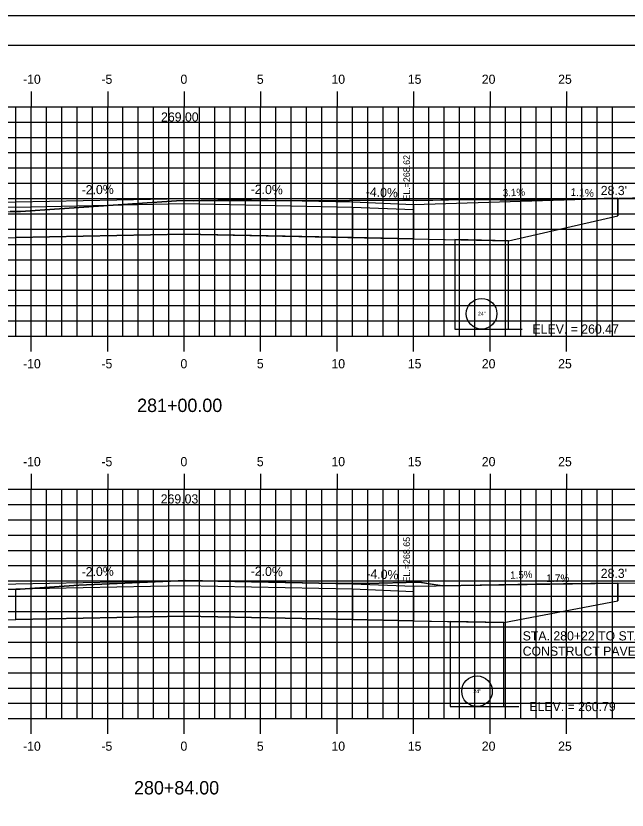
# Model space of a CAD drawing. Extents: x 855344 to 855514, y 366268 to 366378.
# Drawn here: x 855416.1 to 855456.1, y 366326.3 to 366378.2 of the extents above; entities that cross this region are included whole.
import ezdxf

# ---------------------------------------------------------------- set-up
doc = ezdxf.new("R2010")
doc.units = 0
for name, color, linetype in [('ANNOTATION', 7, 'Continuous'), ('BORDER', 7, 'Continuous'), ('D_Roadway_Centerline', 7, 'Continuous'), ('D_Roadway_Centerline_Text', 7, 'Continuous'), ('D_Roadway_Drive_Gravel_RT', 7, 'Continuous'), ('D_Roadway_Drive_SubGrade', 7, 'Continuous'), ('D_Roadway_Edge_Shoulder', 7, 'Continuous'), ('D_Roadway_SubGrade', 7, 'Continuous'), ('D_Text_Monospaced', 7, 'Continuous'), ('D_Text_Standard', 7, 'Continuous'), ('H_V ANNOTATION', 7, 'Continuous'), ('JUNK COM EXC', 7, 'Continuous'), ('junk strct exc', 7, 'Continuous'), ('MAJOR', 7, 'Continuous'), ('MINOR', 7, 'Continuous'), ('PDRAIN', 7, 'Continuous'), ('PLOT BOUNDARY', 7, 'Continuous'), ('S_Roadway_Centerline', 7, 'Continuous')]:
    doc.layers.add(name, color=color, linetype=linetype)

msp = doc.modelspace()

# ---------------------------------------------------------------- linework, layer by layer
at = {"layer": 'BORDER'}
msp.add_line((855512.11, 366376.236), (855352.11, 366376.236), dxfattribs=at)
at = {"layer": 'D_Roadway_Centerline'}
msp.add_lwpolyline([(855416.11, 366366.016), (855427.11, 366366.236), (855438.11, 366366.016)], dxfattribs=at)
at = {"layer": 'D_Roadway_Drive_Gravel_RT'}
for p, q in [((855442.107, 366365.856), (855455.456, 366366.263)), ((855442.107, 366340.888), (855455.456, 366341.093))]:
    msp.add_line(p, q, dxfattribs=at)
at = {"layer": 'D_Roadway_Drive_SubGrade'}
for p, q in [((855455.456, 366366.263), (855455.456, 366365.096)), ((855448.302, 366363.479), (855455.456, 366365.096)), ((855442.107, 366363.603), (855448.302, 366363.479)), ((855455.456, 366341.093), (855455.456, 366339.926)), ((855448.002, 366338.517), (855455.456, 366339.926)), ((855442.107, 366338.635), (855448.002, 366338.517))]:
    msp.add_line(p, q, dxfattribs=at)
at = {"layer": 'D_Roadway_Edge_Shoulder'}
for p, q in [((855442.107, 366365.856), (855442.11, 366365.523)), ((855442.107, 366365.856), (855442.107, 366365.523)), ((855442.107, 366340.888), (855442.11, 366340.556)), ((855442.107, 366340.888), (855442.107, 366340.555))]:
    msp.add_line(p, q, dxfattribs=at)
for points in [[(855411.891, 366365.848), (855416.11, 366366.016), (855427.11, 366366.236), (855438.11, 366366.016), (855442.107, 366365.856)], [(855410.728, 366340.834), (855416.11, 366341.049), (855427.11, 366341.268), (855438.11, 366341.048), (855442.107, 366340.888)]]:
    msp.add_lwpolyline(points, dxfattribs=at)
at = {"layer": 'D_Roadway_SubGrade'}
for points in [[(855416.11, 366365.683), (855411.891, 366365.515), (855411.891, 366363.599), (855416.11, 366363.683)], [(855416.11, 366363.683), (855416.11, 366365.683), (855427.11, 366365.903), (855438.11, 366365.683), (855438.11, 366363.683), (855427.11, 366363.903)], [(855438.11, 366365.683), (855442.11, 366365.523), (855442.11, 366363.603), (855438.11, 366363.683)], [(855416.11, 366338.716), (855416.11, 366340.716), (855427.11, 366340.936), (855438.11, 366340.716), (855438.11, 366338.716), (855427.11, 366338.936)], [(855438.11, 366340.716), (855442.11, 366340.556), (855442.11, 366338.636), (855438.11, 366338.716)]]:
    msp.add_lwpolyline(points, close=True, dxfattribs=at)
at = {"layer": 'D_Text_Standard'}
for points in [[(855448.302, 366357.706), (855448.518, 366357.706), (855449.198, 366357.706)], [(855448.002, 366333.026), (855448.314, 366333.026), (855448.994, 366333.026)]]:
    msp.add_lwpolyline(points, dxfattribs=at)
at = {"layer": 'JUNK COM EXC'}
msp.add_lwpolyline([(855410.891, 366363.579), (855416.11, 366363.683), (855427.11, 366363.903), (855442.11, 366363.603), (855443.107, 366363.583), (855448.302, 366363.479), (855455.456, 366365.096), (855455.456, 366366.263), (855450.069, 366366.134), (855445.427, 366366.167), (855443.109, 366366.119), (855442.313, 366366.102), (855441.388, 366366.135), (855437.92, 366366.106), (855427.725, 366366.096), (855427.071, 366366.108), (855426.605, 366366.089), (855416.406, 366365.387), (855415.725, 366365.379)], dxfattribs=at)
msp.add_lwpolyline([(855409.728, 366340.586), (855409.728, 366338.595), (855416.11, 366338.716), (855427.11, 366338.936), (855438.11, 366338.716), (855443.107, 366338.615), (855448.002, 366338.517), (855455.456, 366339.926), (855455.456, 366341.093), (855450.133, 366341.025), (855443.985, 366340.92), (855443.109, 366341.055), (855442.502, 366341.148), (855438.987, 366341.077), (855437.99, 366341.069), (855437.021, 366341.068), (855427.216, 366341.257), (855420.216, 366340.964), (855416.384, 366340.7), (855413.757, 366340.668), (855411.541, 366340.585)], close=True, dxfattribs=at)
at = {"layer": 'junk strct exc'}
for points in [[(855444.802, 366363.549), (855444.802, 366357.706), (855448.302, 366357.706), (855448.302, 366363.479)], [(855444.502, 366338.587), (855444.502, 366333.026), (855448.002, 366333.026), (855448.002, 366338.517)]]:
    msp.add_lwpolyline(points, close=True, dxfattribs=at)
at = {"layer": 'MAJOR'}
for p, q in [((855417.11, 366373.238), (855417.11, 366372.236)), ((855422.11, 366373.238), (855422.11, 366372.236)), ((855427.11, 366373.238), (855427.11, 366372.236)), ((855432.11, 366373.238), (855432.11, 366372.236)), ((855437.11, 366373.238), (855437.11, 366372.236)), ((855442.11, 366373.238), (855442.11, 366372.236)), ((855447.11, 366373.238), (855447.11, 366372.236)), ((855452.11, 366373.238), (855452.11, 366372.236)), ((855357.11, 366372.236), (855497.11, 366372.236)), ((855357.11, 366372.236), (855497.11, 366372.236)), ((855417.11, 366357.236), (855417.11, 366372.236)), ((855422.11, 366357.236), (855422.11, 366372.236)), ((855427.11, 366357.236), (855427.11, 366372.236)), ((855432.11, 366357.236), (855432.11, 366372.236)), ((855437.11, 366357.236), (855437.11, 366372.236)), ((855442.11, 366357.236), (855442.11, 366372.236)), ((855447.11, 366357.236), (855447.11, 366372.236)), ((855452.11, 366357.236), (855452.11, 366372.236)), ((855357.11, 366367.236), (855497.11, 366367.236)), ((855357.11, 366362.236), (855497.11, 366362.236)), ((855357.11, 366357.236), (855497.11, 366357.236)), ((855357.11, 366357.236), (855497.11, 366357.236)), ((855417.11, 366356.234), (855417.11, 366357.236)), ((855422.11, 366356.234), (855422.11, 366357.236)), ((855427.11, 366356.234), (855427.11, 366357.236)), ((855432.11, 366356.234), (855432.11, 366357.236)), ((855437.11, 366356.234), (855437.11, 366357.236)), ((855442.11, 366356.234), (855442.11, 366357.236)), ((855447.11, 366356.234), (855447.11, 366357.236)), ((855452.11, 366356.234), (855452.11, 366357.236)), ((855417.11, 366348.238), (855417.11, 366347.236)), ((855422.11, 366348.238), (855422.11, 366347.236)), ((855427.11, 366348.238), (855427.11, 366347.236)), ((855432.11, 366348.238), (855432.11, 366347.236)), ((855437.11, 366348.238), (855437.11, 366347.236)), ((855442.11, 366348.238), (855442.11, 366347.236)), ((855447.11, 366348.238), (855447.11, 366347.236)), ((855452.11, 366348.238), (855452.11, 366347.236)), ((855357.11, 366347.236), (855497.11, 366347.236)), ((855357.11, 366347.236), (855497.11, 366347.236)), ((855417.11, 366332.236), (855417.11, 366347.236)), ((855422.11, 366332.236), (855422.11, 366347.236)), ((855427.11, 366332.236), (855427.11, 366347.236)), ((855432.11, 366332.236), (855432.11, 366347.236)), ((855437.11, 366332.236), (855437.11, 366347.236)), ((855442.11, 366332.236), (855442.11, 366347.236)), ((855447.11, 366332.236), (855447.11, 366347.236)), ((855452.11, 366332.236), (855452.11, 366347.236)), ((855357.11, 366342.236), (855497.11, 366342.236)), ((855357.11, 366337.236), (855497.11, 366337.236)), ((855357.11, 366332.236), (855497.11, 366332.236)), ((855357.11, 366332.236), (855497.11, 366332.236)), ((855417.11, 366331.234), (855417.11, 366332.236)), ((855422.11, 366331.234), (855422.11, 366332.236)), ((855427.11, 366331.234), (855427.11, 366332.236)), ((855432.11, 366331.234), (855432.11, 366332.236)), ((855437.11, 366331.234), (855437.11, 366332.236)), ((855442.11, 366331.234), (855442.11, 366332.236)), ((855447.11, 366331.234), (855447.11, 366332.236)), ((855452.11, 366331.234), (855452.11, 366332.236))]:
    msp.add_line(p, q, dxfattribs=at)
at = {"layer": 'MINOR'}
for p, q in [((855416.11, 366357.236), (855416.11, 366372.236)), ((855418.11, 366357.236), (855418.11, 366372.236)), ((855419.11, 366357.236), (855419.11, 366372.236)), ((855420.11, 366357.236), (855420.11, 366372.236)), ((855421.11, 366357.236), (855421.11, 366372.236)), ((855423.11, 366357.236), (855423.11, 366372.236)), ((855424.11, 366357.236), (855424.11, 366372.236)), ((855425.11, 366357.236), (855425.11, 366372.236)), ((855426.11, 366357.236), (855426.11, 366372.236)), ((855428.11, 366357.236), (855428.11, 366372.236)), ((855429.11, 366357.236), (855429.11, 366372.236)), ((855430.11, 366357.236), (855430.11, 366372.236)), ((855431.11, 366357.236), (855431.11, 366372.236)), ((855433.11, 366357.236), (855433.11, 366372.236)), ((855434.11, 366357.236), (855434.11, 366372.236)), ((855435.11, 366357.236), (855435.11, 366372.236)), ((855436.11, 366357.236), (855436.11, 366372.236)), ((855438.11, 366357.236), (855438.11, 366372.236)), ((855439.11, 366357.236), (855439.11, 366372.236)), ((855440.11, 366357.236), (855440.11, 366372.236)), ((855441.11, 366357.236), (855441.11, 366372.236)), ((855443.11, 366357.236), (855443.11, 366372.236)), ((855444.11, 366357.236), (855444.11, 366372.236)), ((855445.11, 366357.236), (855445.11, 366372.236)), ((855446.11, 366357.236), (855446.11, 366372.236)), ((855448.11, 366357.236), (855448.11, 366372.236)), ((855449.11, 366357.236), (855449.11, 366372.236)), ((855450.11, 366357.236), (855450.11, 366372.236)), ((855451.11, 366357.236), (855451.11, 366372.236)), ((855453.11, 366357.236), (855453.11, 366372.236)), ((855454.11, 366357.236), (855454.11, 366372.236)), ((855455.11, 366357.236), (855455.11, 366372.236)), ((855357.11, 366371.236), (855497.11, 366371.236)), ((855357.11, 366370.236), (855497.11, 366370.236)), ((855357.11, 366369.236), (855497.11, 366369.236)), ((855357.11, 366368.236), (855497.11, 366368.236)), ((855357.11, 366366.236), (855497.11, 366366.236)), ((855357.11, 366365.236), (855497.11, 366365.236)), ((855357.11, 366364.236), (855497.11, 366364.236)), ((855357.11, 366363.236), (855497.11, 366363.236)), ((855357.11, 366361.236), (855497.11, 366361.236)), ((855357.11, 366360.236), (855497.11, 366360.236)), ((855357.11, 366359.236), (855497.11, 366359.236)), ((855357.11, 366358.236), (855497.11, 366358.236)), ((855418.11, 366332.236), (855418.11, 366347.236)), ((855419.11, 366332.236), (855419.11, 366347.236)), ((855420.11, 366332.236), (855420.11, 366347.236)), ((855421.11, 366332.236), (855421.11, 366347.236)), ((855423.11, 366332.236), (855423.11, 366347.236)), ((855424.11, 366332.236), (855424.11, 366347.236)), ((855425.11, 366332.236), (855425.11, 366347.236)), ((855426.11, 366332.236), (855426.11, 366347.236)), ((855428.11, 366332.236), (855428.11, 366347.236)), ((855429.11, 366332.236), (855429.11, 366347.236)), ((855430.11, 366332.236), (855430.11, 366347.236)), ((855431.11, 366332.236), (855431.11, 366347.236)), ((855433.11, 366332.236), (855433.11, 366347.236)), ((855434.11, 366332.236), (855434.11, 366347.236)), ((855435.11, 366332.236), (855435.11, 366347.236)), ((855436.11, 366332.236), (855436.11, 366347.236)), ((855438.11, 366332.236), (855438.11, 366347.236)), ((855439.11, 366332.236), (855439.11, 366347.236)), ((855440.11, 366332.236), (855440.11, 366347.236)), ((855441.11, 366332.236), (855441.11, 366347.236)), ((855443.11, 366332.236), (855443.11, 366347.236)), ((855444.11, 366332.236), (855444.11, 366347.236)), ((855445.11, 366332.236), (855445.11, 366347.236)), ((855446.11, 366332.236), (855446.11, 366347.236)), ((855448.11, 366332.236), (855448.11, 366347.236)), ((855449.11, 366332.236), (855449.11, 366347.236)), ((855450.11, 366332.236), (855450.11, 366347.236)), ((855451.11, 366332.236), (855451.11, 366347.236)), ((855453.11, 366332.236), (855453.11, 366347.236)), ((855454.11, 366332.236), (855454.11, 366347.236)), ((855455.11, 366332.236), (855455.11, 366347.236)), ((855357.11, 366346.236), (855497.11, 366346.236)), ((855357.11, 366345.236), (855497.11, 366345.236)), ((855357.11, 366344.236), (855497.11, 366344.236)), ((855357.11, 366343.236), (855497.11, 366343.236)), ((855357.11, 366341.236), (855497.11, 366341.236)), ((855357.11, 366340.236), (855497.11, 366340.236)), ((855357.11, 366339.236), (855497.11, 366339.236)), ((855357.11, 366338.236), (855497.11, 366338.236)), ((855357.11, 366336.236), (855497.11, 366336.236)), ((855357.11, 366335.236), (855497.11, 366335.236)), ((855357.11, 366334.236), (855497.11, 366334.236)), ((855357.11, 366333.236), (855497.11, 366333.236))]:
    msp.add_line(p, q, dxfattribs=at)
at = {"layer": 'PDRAIN'}
for points in [[(855444.802, 366363.549), (855444.802, 366357.706), (855448.302, 366357.706), (855448.302, 366363.479)], [(855444.502, 366338.587), (855444.502, 366333.026), (855448.002, 366333.026), (855448.002, 366338.517)]]:
    msp.add_lwpolyline(points, dxfattribs=at)
for centre in [(855446.552, 366358.706), (855446.252, 366334.026)]:
    msp.add_circle(centre, 1, dxfattribs=at)
at = {"layer": 'PLOT BOUNDARY'}
msp.add_lwpolyline([(855344.016, 366268.177), (855514.016, 366268.177), (855514.016, 366378.177), (855344.016, 366378.177)], close=True, dxfattribs=at)
at = {"layer": 'S_Roadway_Centerline'}
for points in [[(855399.796, 366366.557), (855402.343, 366366.557), (855402.643, 366366.369), (855402.938, 366365.51), (855403.859, 366365.474), (855407.633, 366365.705), (855409.284, 366365.542), (855411.944, 366365.344), (855412.088, 366365.206), (855415.725, 366365.379), (855416.406, 366365.387), (855426.605, 366366.089), (855427.071, 366366.108), (855427.725, 366366.096), (855437.92, 366366.106), (855441.388, 366366.135), (855442.313, 366366.102), (855445.427, 366366.167), (855450.069, 366366.134), (855463.667, 366366.46)], [(855384.275, 366339.699), (855388.432, 366339.882), (855400.711, 366340.39), (855405.927, 366340.564), (855407.101, 366340.624), (855408.927, 366340.586), (855411.541, 366340.585), (855413.757, 366340.668), (855416.384, 366340.7), (855420.216, 366340.964), (855427.216, 366341.257), (855437.021, 366341.068), (855437.99, 366341.069), (855438.987, 366341.077), (855442.502, 366341.148), (855443.985, 366340.92), (855449.999, 366341.018), (855450.133, 366341.025), (855450.439, 366341.026), (855468.024, 366341.26), (855473.254, 366341.359), (855474.777, 366341.358), (855474.83, 366341.346)]]:
    msp.add_lwpolyline(points, dxfattribs=at)

# ---------------------------------------------------------------- texts
at = {"layer": 'ANNOTATION'}
for s, rotation, p in [('-2.0%', 1.1458, (855420.413, 366366.502)), ('-2.0%', 358.8542, (855431.453, 366366.549)), ('-4.0%', 357.7095, (855438.972, 366366.382)), ('-2.0%', 1.1458, (855420.413, 366341.535)), ('-2.0%', 358.8542, (855431.453, 366341.582)), ('-4.0%', 357.7095, (855439.008, 366341.413))]:
    msp.add_text(s, height=0.6, rotation=rotation, dxfattribs=at).set_placement(p)
for s, p in [('STA. 280+22 TO STA. 281+50 RT', (855449.237, 366337.348)), ('CONSTRUCT PAVED PARKING AREA.', (855449.237, 366336.348))]:
    msp.add_text(s, height=0.6, dxfattribs=at).set_placement(p)
at = {"layer": 'D_Roadway_Centerline_Text'}
for s, p in [('269.00', (855425.601, 366371.268)), ('269.03', (855425.577, 366346.3))]:
    msp.add_text(s, height=0.6, dxfattribs=at).set_placement(p)
at = {"layer": 'D_Roadway_Drive_Gravel_RT'}
for s, p in [('3.1%', (855447.942, 366366.366)), ('1.5%', (855448.423, 366341.371))]:
    msp.add_text(s, height=0.48, rotation=2.2906, dxfattribs=at).set_placement(p)
at = {"layer": 'D_Text_Monospaced'}
for s, rotation, p in [('1.1%', 356.9436, (855452.359, 366366.417)), ('1.7%', 359.9682, (855450.773, 366341.16))]:
    msp.add_text(s, height=0.5, rotation=rotation, dxfattribs=at).set_placement(p)
at = {"layer": 'D_Text_Standard'}
for s, p in [(' EL.=268.62', (855441.871, 366365.941)), (' EL.=268.65', (855441.871, 366340.973))]:
    msp.add_text(s, height=0.4335, rotation=90, dxfattribs=at).set_placement(p)
for s, p in [("28.3'", (855454.34, 366366.462)), ('ELEV. = 260.47', (855449.878, 366357.406)), ("28.3'", (855454.34, 366341.433)), ('ELEV. = 260.79', (855449.674, 366332.726))]:
    msp.add_text(s, height=0.6, dxfattribs=at).set_placement(p)
at = {"layer": 'H_V ANNOTATION'}
for s, height, p in [('-10', 0.6, (855416.575, 366373.736)), ('-5', 0.6, (855421.7, 366373.736)), ('0', 0.6, (855426.869, 366373.736)), ('5', 0.6, (855431.861, 366373.736)), ('10', 0.6, (855436.735, 366373.736)), ('15', 0.6, (855441.727, 366373.736)), ('20', 0.6, (855446.564, 366373.736)), ('25', 0.6, (855451.556, 366373.736)), ('-10', 0.6, (855416.575, 366355.136)), ('-5', 0.6, (855421.7, 366355.136)), ('0', 0.6, (855426.869, 366355.136)), ('5', 0.6, (855431.861, 366355.136)), ('10', 0.6, (855436.735, 366355.136)), ('15', 0.6, (855441.727, 366355.136)), ('20', 0.6, (855446.564, 366355.136)), ('25', 0.6, (855451.556, 366355.136)), ('281+00.00', 0.875, (855424.035, 366352.28)), ('-10', 0.6, (855416.575, 366348.736)), ('-5', 0.6, (855421.7, 366348.736)), ('0', 0.6, (855426.869, 366348.736)), ('5', 0.6, (855431.861, 366348.736)), ('10', 0.6, (855436.735, 366348.736)), ('15', 0.6, (855441.727, 366348.736)), ('20', 0.6, (855446.564, 366348.736)), ('25', 0.6, (855451.556, 366348.736)), ('-10', 0.6, (855416.575, 366330.136)), ('-5', 0.6, (855421.7, 366330.136)), ('0', 0.6, (855426.869, 366330.136)), ('5', 0.6, (855431.861, 366330.136)), ('10', 0.6, (855436.735, 366330.136)), ('15', 0.6, (855441.727, 366330.136)), ('20', 0.6, (855446.564, 366330.136)), ('25', 0.6, (855451.556, 366330.136)), ('280+84.00', 0.875, (855423.832, 366327.28))]:
    msp.add_text(s, height=height, dxfattribs=at).set_placement(p)
at = {"layer": 'PDRAIN'}
for p in [(855446.31, 366358.581), (855446.01, 366333.901)]:
    msp.add_text('24"', height=0.25, dxfattribs=at).set_placement(p)
at = {"layer": 'S_Roadway_Centerline'}
for s, p in [('L', (855427.063, 366366.101)), ('C', (855427.066, 366366.108)), ('C', (855427.211, 366341.257)), ('L', (855427.216, 366341.249))]:
    msp.add_text(s, height=0.0146, dxfattribs=at).set_placement(p)

doc.saveas('drawing.dxf')
